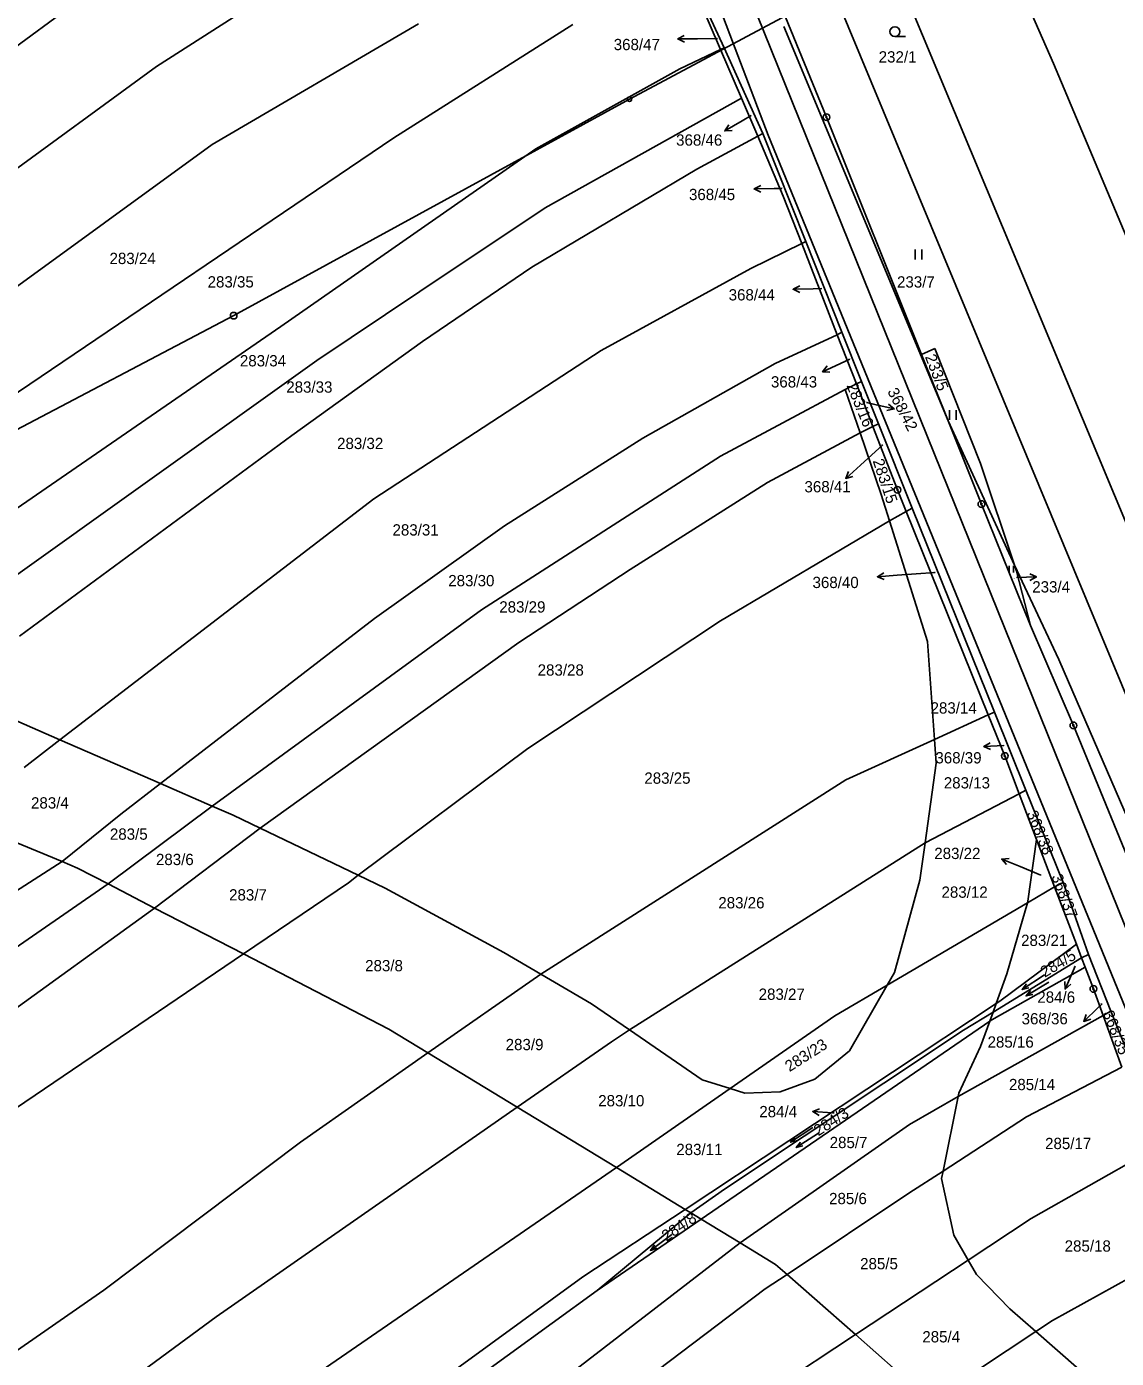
# Model space of a CAD drawing. Extents: x -762263 to -760336, y -1154405 to -1152076.
# Drawn here: x -761541.7 to -761377.6, y -1152988.8 to -1152788.2 of the extents above; entities that cross this region are included whole.
import ezdxf

# ---------------------------------------------------------------- set-up
doc = ezdxf.new("R2010")
doc.units = 0
for name, color, linetype in [('Vrstva 1', 7, 'Continuous'), ('Vrstva 12', 7, 'Continuous'), ('Vrstva 16', 7, 'Continuous'), ('Vrstva 18', 7, 'Continuous'), ('Vrstva 24', 7, 'Continuous'), ('Vrstva 25', 7, 'Continuous'), ('Vrstva 26', 7, 'Continuous'), ('Vrstva 4', 7, 'Continuous'), ('Vrstva 6', 7, 'Continuous')]:
    doc.layers.add(name, color=color, linetype=linetype)

msp = doc.modelspace()

# ---------------------------------------------------------------- linework, layer by layer
at = {"layer": 'Vrstva 1'}
for p, q in [((-761359.06, -1152904.05), (-761421.84, -1152753.46)), ((-761365.51, -1152914.59), (-761431.48, -1152755.68)), ((-761421.27, -1152801.84), (-761434.72, -1152768.97)), ((-761522.15, -1152794.2), (-761488.72, -1152772.8)), ((-761443.12, -1152777.85), (-761437.22, -1152791.63)), ((-761442.95, -1152777.74), (-761436.7, -1152791.39)), ((-761530.76, -1152781.96), (-761631.52, -1152856.45)), ((-761482.68, -1152787.79), (-761513.77, -1152805.94)), ((-761427.68, -1152788.2), (-761402.97, -1152847.56)), ((-761437.22, -1152791.63), (-761436.7, -1152791.39)), ((-761434.07, -1152798.99), (-761437.22, -1152791.63)), ((-761436.7, -1152791.39), (-761430.84, -1152804.3)), ((-761616.57, -1152863.14), (-761522.15, -1152794.2)), ((-761431.62, -1152804.72), (-761434.07, -1152798.99)), ((-761421.27, -1152801.84), (-761406.97, -1152837.57)), ((-761430.84, -1152804.3), (-761431.62, -1152804.72)), ((-761427.77, -1152813.73), (-761431.62, -1152804.72)), ((-761430.84, -1152804.3), (-761424.39, -1152820.54)), ((-761513.77, -1152805.94), (-761600.5, -1152869.06)), ((-761425, -1152820.84), (-761427.77, -1152813.73)), ((-761424.39, -1152820.54), (-761425, -1152820.84)), ((-761425, -1152820.84), (-761419.66, -1152834.6)), ((-761418.98, -1152834.22), (-761424.39, -1152820.54)), ((-761419.66, -1152834.6), (-761418.98, -1152834.22)), ((-761419.66, -1152834.6), (-761416.77, -1152842.02)), ((-761416, -1152841.65), (-761418.98, -1152834.22)), ((-761406.97, -1152837.57), (-761404.98, -1152836.67)), ((-761398.08, -1152853.99), (-761404.98, -1152836.67)), ((-761406.97, -1152837.57), (-761402.97, -1152847.56)), ((-761416.77, -1152842.02), (-761418.44, -1152842.83)), ((-761418.44, -1152842.83), (-761416.19, -1152849.39)), ((-761416.77, -1152842.02), (-761416, -1152841.65)), ((-761416.77, -1152842.02), (-761414.28, -1152848.44)), ((-761413.45, -1152848.03), (-761416, -1152841.65)), ((-761416.19, -1152849.39), (-761414.28, -1152848.44)), ((-761414.28, -1152848.44), (-761413.45, -1152848.03)), ((-761414.28, -1152848.44), (-761410.58, -1152857.95)), ((-761408.38, -1152860.71), (-761413.45, -1152848.03)), ((-761402.97, -1152847.56), (-761397.95, -1152860.1)), ((-761392.98, -1152869.29), (-761402.97, -1152847.56)), ((-761413.02, -1152858.65), (-761416.19, -1152849.39)), ((-761392.98, -1152869.29), (-761398.08, -1152853.99)), ((-761411.76, -1152862.64), (-761413.02, -1152858.65)), ((-761410.58, -1152857.95), (-761409.26, -1152861.24)), ((-761409.26, -1152861.24), (-761408.38, -1152860.71)), ((-761396, -1152891.44), (-761408.38, -1152860.71)), ((-761390.56, -1152878.39), (-761397.95, -1152860.1)), ((-761411.76, -1152862.64), (-761409.26, -1152861.24)), ((-761406.04, -1152880.82), (-761411.76, -1152862.64)), ((-761409.26, -1152861.24), (-761396.92, -1152891.86)), ((-761392.67, -1152870.22), (-761392.98, -1152869.29)), ((-761390.56, -1152878.39), (-761392.67, -1152870.22)), ((-761384.1, -1152893.43), (-761390.56, -1152878.39)), ((-761405.02, -1152895.55), (-761406.04, -1152880.82)), ((-761553.98, -1152888.06), (-761536.69, -1152895.6)), ((-761405.02, -1152895.55), (-761396.92, -1152891.86)), ((-761396.92, -1152891.86), (-761396, -1152891.44)), ((-761396.92, -1152891.86), (-761394.43, -1152898.04)), ((-761391.26, -1152903.19), (-761396, -1152891.44)), ((-761384.1, -1152893.43), (-761369.9, -1152928.1)), ((-761536.69, -1152895.6), (-761542.07, -1152899.78)), ((-761521.55, -1152902.2), (-761536.69, -1152895.6)), ((-761404.77, -1152899.14), (-761405.02, -1152895.55)), ((-761394.43, -1152898.04), (-761392.27, -1152903.72)), ((-761406.43, -1152911.14), (-761404.77, -1152899.14)), ((-761527.52, -1152906.82), (-761521.55, -1152902.2)), ((-761521.55, -1152902.2), (-761513.75, -1152905.6)), ((-761406.43, -1152911.14), (-761392.27, -1152903.72)), ((-761392.27, -1152903.72), (-761391.26, -1152903.19)), ((-761392.27, -1152903.72), (-761389.65, -1152910.6)), ((-761385.66, -1152917.1), (-761391.26, -1152903.19)), ((-761536.35, -1152913.95), (-761527.52, -1152906.82)), ((-761513.75, -1152905.6), (-761529.44, -1152917.29)), ((-761510.61, -1152906.97), (-761513.75, -1152905.6)), ((-761506.54, -1152908.92), (-761510.61, -1152906.97)), ((-761552.17, -1152907.36), (-761536.35, -1152913.95)), ((-761522.42, -1152920.93), (-761506.54, -1152908.92)), ((-761506.54, -1152908.92), (-761491.78, -1152915.98)), ((-761407.21, -1152916.73), (-761406.43, -1152911.14)), ((-761389.65, -1152910.6), (-761390.94, -1152919.91)), ((-761389.65, -1152910.6), (-761386.93, -1152917.76)), ((-761534.03, -1152914.92), (-761536.35, -1152913.95)), ((-761529.44, -1152917.29), (-761534.03, -1152914.92)), ((-761493.25, -1152917.15), (-761509.05, -1152927.85)), ((-761491.78, -1152915.98), (-761493.25, -1152917.15)), ((-761491.78, -1152915.98), (-761487.69, -1152917.94)), ((-761411.03, -1152930.63), (-761407.21, -1152916.73)), ((-761386.93, -1152917.76), (-761385.66, -1152917.1)), ((-761381.82, -1152927.94), (-761385.66, -1152917.1)), ((-761529.44, -1152917.29), (-761522.42, -1152920.93)), ((-761487.69, -1152917.94), (-761469.83, -1152927.65)), ((-761386.93, -1152917.76), (-761391.01, -1152920.15)), ((-761383.65, -1152926.38), (-761386.93, -1152917.76)), ((-761509.05, -1152927.85), (-761522.42, -1152920.93)), ((-761391.01, -1152920.15), (-761412.14, -1152932.56)), ((-761394.12, -1152930.85), (-761391.01, -1152920.15)), ((-761390.94, -1152919.91), (-761391.01, -1152920.15)), ((-761383.65, -1152926.38), (-761395.19, -1152934.94)), ((-761382.87, -1152928.44), (-761383.65, -1152926.38)), ((-761487.15, -1152939.18), (-761509.05, -1152927.85)), ((-761469.83, -1152927.65), (-761464.29, -1152930.88)), ((-761396.2, -1152936.6), (-761382.87, -1152928.44)), ((-761382.87, -1152928.44), (-761381.82, -1152927.94)), ((-761382.34, -1152929.84), (-761382.87, -1152928.44)), ((-761378.44, -1152936.46), (-761381.82, -1152927.94)), ((-761464.29, -1152930.88), (-761481.27, -1152942.76)), ((-761464.29, -1152930.88), (-761456.63, -1152935.35)), ((-761412.14, -1152932.56), (-761411.03, -1152930.63)), ((-761396.36, -1152937.75), (-761382.34, -1152929.84)), ((-761395.73, -1152935.3), (-761394.12, -1152930.85)), ((-761382.34, -1152929.84), (-761381.09, -1152933.12)), ((-761420, -1152937.18), (-761412.14, -1152932.56)), ((-761412.14, -1152932.56), (-761417.82, -1152942.45)), ((-761381.09, -1152933.12), (-761379.64, -1152937.13)), ((-761395.19, -1152934.94), (-761395.73, -1152935.3)), ((-761456.63, -1152935.35), (-761450.92, -1152939.28)), ((-761442.56, -1152966.31), (-761395.73, -1152935.3)), ((-761435.76, -1152948.12), (-761420, -1152937.18)), ((-761400.66, -1152939.33), (-761396.2, -1152936.6)), ((-761396.2, -1152936.6), (-761396.7, -1152937.98)), ((-761395.73, -1152935.3), (-761396.2, -1152936.6)), ((-761379.64, -1152937.13), (-761378.44, -1152936.46)), ((-761379.64, -1152937.13), (-761376.82, -1152944.89)), ((-761375.4, -1152944.06), (-761378.44, -1152936.46)), ((-761481.27, -1152942.76), (-761487.15, -1152939.18)), ((-761440.13, -1152967.78), (-761396.7, -1152937.98)), ((-761396.7, -1152937.98), (-761398.08, -1152941.79)), ((-761396.7, -1152937.98), (-761396.36, -1152937.75)), ((-761453.65, -1152941.06), (-761467.83, -1152950.93)), ((-761450.92, -1152939.28), (-761453.65, -1152941.06)), ((-761439.98, -1152946.79), (-761450.92, -1152939.28)), ((-761436.62, -1152963.26), (-761400.66, -1152939.33)), ((-761467.83, -1152950.93), (-761481.27, -1152942.76)), ((-761417.82, -1152942.45), (-761423.02, -1152946.7)), ((-761398.08, -1152941.79), (-761401.34, -1152948.8)), ((-761435.76, -1152948.12), (-761439.98, -1152946.79)), ((-761423.02, -1152946.7), (-761428.23, -1152948.59)), ((-761452.9, -1152960.02), (-761435.76, -1152948.12)), ((-761433.56, -1152948.82), (-761435.76, -1152948.12)), ((-761428.23, -1152948.59), (-761433.56, -1152948.82)), ((-761401.34, -1152948.8), (-761401.44, -1152949.31)), ((-761467.83, -1152950.93), (-761452.9, -1152960.02)), ((-761408.78, -1152953.55), (-761401.44, -1152949.31)), ((-761401.44, -1152949.31), (-761403.72, -1152960.54)), ((-761434.28, -1152971.34), (-761408.78, -1152953.55)), ((-761442.56, -1152966.31), (-761452.9, -1152960.02)), ((-761408.87, -1152963.89), (-761403.72, -1152960.54)), ((-761403.72, -1152960.54), (-761403.95, -1152961.67)), ((-761441.67, -1152966.85), (-761436.62, -1152963.26)), ((-761403.95, -1152961.67), (-761402.11, -1152970.21)), ((-761427.21, -1152976.11), (-761408.87, -1152963.89)), ((-761457.93, -1152976.48), (-761442.56, -1152966.31)), ((-761442.56, -1152966.31), (-761441.67, -1152966.85)), ((-761441.67, -1152966.85), (-761440.13, -1152967.78)), ((-761455.81, -1152978.54), (-761440.13, -1152967.78)), ((-761440.13, -1152967.78), (-761434.28, -1152971.34)), ((-761402.11, -1152970.21), (-761399.94, -1152973.96)), ((-761428.93, -1152974.6), (-761434.28, -1152971.34)), ((-761427.21, -1152976.11), (-761428.93, -1152974.6)), ((-761416.92, -1152985.16), (-761399.94, -1152973.96)), ((-761399.94, -1152973.96), (-761398.68, -1152976.14)), ((-761550.95, -1153044.04), (-761457.93, -1152976.48)), ((-761416.92, -1152985.16), (-761427.21, -1152976.11)), ((-761398.68, -1152976.14), (-761393.65, -1152981.27)), ((-761455.81, -1152978.54), (-761548.99, -1153046.04)), ((-761393.65, -1152981.27), (-761389.73, -1152984.7)), ((-761405.57, -1152995.15), (-761416.92, -1152985.16)), ((-761405.57, -1152995.15), (-761389.73, -1152984.7)), ((-761389.73, -1152984.7), (-761379.16, -1152993.96))]:
    msp.add_line(p, q, dxfattribs=at)
at = {"layer": 'Vrstva 12'}
for p, q in [((-761450.93, -1152799.12), (-761389.45, -1152766.26)), ((-761450.93, -1152799.12), (-761510.52, -1152831.73)), ((-761510.52, -1152831.73), (-761578.61, -1152867.5))]:
    msp.add_line(p, q, dxfattribs=at)
at = {"layer": 'Vrstva 16'}
for p, q in [((-761443.67, -1152790.054), (-761440.67, -1152790.02)), ((-761437.67, -1152789.98), (-761440.67, -1152790.02)), ((-761436.592, -1152803.904), (-761433.99, -1152802.41)), ((-761432.6, -1152801.61), (-761433.99, -1152802.41)), ((-761432.17, -1152812.632), (-761429.17, -1152812.58)), ((-761428, -1152812.56), (-761429.17, -1152812.58)), ((-761426.289, -1152827.744), (-761423.29, -1152827.68)), ((-761421.96, -1152827.65), (-761423.29, -1152827.68)), ((-761421.86, -1152840.185), (-761419.14, -1152838.92)), ((-761417.77, -1152838.28), (-761419.14, -1152838.92)), ((-761415.27, -1152844.8), (-761414, -1152845.09)), ((-761411.077, -1152845.766), (-761414, -1152845.09)), ((-761412.77, -1152851.2), (-761416.15, -1152854.23)), ((-761418.383, -1152856.233), (-761416.15, -1152854.23)), ((-761413.612, -1152871.052), (-761410.62, -1152870.83)), ((-761404.91, -1152870.4), (-761410.62, -1152870.83)), ((-761389.671, -1152871.075), (-761392.67, -1152871.14)), ((-761397.587, -1152896.61), (-761394.59, -1152896.48)), ((-761394.57, -1152896.48), (-761394.59, -1152896.48)), ((-761394.894, -1152913.557), (-761392.12, -1152914.7)), ((-761388.99, -1152915.99), (-761392.12, -1152914.7)), ((-761385.351, -1152933.135), (-761384.14, -1152930.39)), ((-761383.84, -1152929.71), (-761384.14, -1152930.39)), ((-761382.55, -1152938.012), (-761380.39, -1152935.93)), ((-761379.78, -1152935.34), (-761380.39, -1152935.93)), ((-761423.344, -1152951.595), (-761420.35, -1152951.78)), ((-761420.12, -1152951.79), (-761420.35, -1152951.78))]:
    msp.add_line(p, q, dxfattribs=at)
for points in [[(-761442.664, -1152790.542), (-761443.67, -1152790.054), (-761442.675, -1152789.542)], [(-761435.475, -1152803.839), (-761436.592, -1152803.904), (-761435.973, -1152802.972)], [(-761431.161, -1152813.114), (-761432.17, -1152812.632), (-761431.178, -1152812.114)], [(-761425.279, -1152828.222), (-761426.289, -1152827.744), (-761425.3, -1152827.223)], [(-761420.743, -1152840.217), (-761421.86, -1152840.185), (-761421.164, -1152839.31)], [(-761411.939, -1152845.054), (-761411.077, -1152845.766), (-761412.164, -1152846.028)], [(-761417.305, -1152855.938), (-761418.383, -1152856.233), (-761417.973, -1152855.193)], [(-761412.577, -1152871.477), (-761413.612, -1152871.052), (-761412.652, -1152870.48)], [(-761390.681, -1152870.597), (-761389.671, -1152871.075), (-761390.66, -1152871.597)], [(-761396.567, -1152897.066), (-761397.587, -1152896.61), (-761396.61, -1152896.067)], [(-761394.16, -1152914.4), (-761394.894, -1152913.557), (-761393.779, -1152913.476)], [(-761384.49, -1152932.422), (-761385.351, -1152933.135), (-761385.405, -1152932.018)], [(-761381.483, -1152937.678), (-761382.55, -1152938.012), (-761382.177, -1152936.958)], [(-761422.377, -1152952.156), (-761423.344, -1152951.595), (-761422.315, -1152951.157)]]:
    msp.add_lwpolyline(points, dxfattribs=at)
at = {"layer": 'Vrstva 24'}
for centre, radius in [((-761421.27, -1152801.84), 0.5), ((-761421.27, -1152801.84), 0.1), ((-761410.58, -1152857.95), 0.5), ((-761410.58, -1152857.95), 0.1), ((-761397.95, -1152860.1), 0.5), ((-761397.95, -1152860.1), 0.1), ((-761384.1, -1152893.43), 0.5), ((-761384.1, -1152893.43), 0.1), ((-761394.43, -1152898.04), 0.5), ((-761394.43, -1152898.04), 0.1), ((-761381.09, -1152933.12), 0.5), ((-761381.09, -1152933.12), 0.1)]:
    msp.add_circle(centre, radius, dxfattribs=at)
at = {"layer": 'Vrstva 25'}
for p, q in [((-761410.97, -1152789.71), (-761409.37, -1152789.71)), ((-761407.94, -1152823.25), (-761407.94, -1152821.75)), ((-761406.94, -1152823.25), (-761406.94, -1152821.75)), ((-761402.73, -1152847.44), (-761402.73, -1152845.94)), ((-761401.73, -1152847.44), (-761401.73, -1152845.94)), ((-761393.765, -1152870.41), (-761393.765, -1152869.405)), ((-761393.095, -1152870.41), (-761393.095, -1152869.405))]:
    msp.add_line(p, q, dxfattribs=at)
for points in [[(-761388.448, -1152930.999), (-761391.812, -1152933.201), (-761390.788, -1152932.931)], [(-761391.812, -1152933.201), (-761391.154, -1152932.37)], [(-761387.788, -1152932.092), (-761391.232, -1152934.168), (-761390.198, -1152933.936)], [(-761391.232, -1152934.168), (-761390.544, -1152933.362)], [(-761423.312, -1152953.993), (-761426.668, -1152956.207), (-761425.644, -1152955.933)], [(-761422.465, -1152954.825), (-761425.835, -1152957.015), (-761424.81, -1152956.749)], [(-761426.668, -1152956.207), (-761426.013, -1152955.374)], [(-761425.835, -1152957.015), (-761425.175, -1152956.187)], [(-761444.557, -1152970.101), (-761447.783, -1152972.499), (-761446.777, -1152972.169)], [(-761447.783, -1152972.499), (-761447.176, -1152971.631)]]:
    msp.add_lwpolyline(points, dxfattribs=at)
msp.add_circle((-761410.97, -1152788.96), 0.75, dxfattribs=at)
at = {"layer": 'Vrstva 26'}
for centre, radius in [((-761450.93, -1152799.12), 0.335), ((-761510.52, -1152831.73), 0.5)]:
    msp.add_circle(centre, radius, dxfattribs=at)
at = {"layer": 'Vrstva 4'}
for p, q in [((-761435.81, -1152776.3), (-761364.68, -1152952.56)), ((-761440.38, -1152777.38), (-761430.06, -1152804.55)), ((-761371.29, -1152948.19), (-761430.06, -1152804.55))]:
    msp.add_line(p, q, dxfattribs=at)
at = {"layer": 'Vrstva 6'}
for p, q in [((-761396.79, -1152771.69), (-761387.09, -1152793.76)), ((-761486.39, -1152804.93), (-761459.45, -1152787.9)), ((-761443.33, -1152794.57), (-761437.22, -1152791.63)), ((-761465.01, -1152806.63), (-761443.33, -1152794.57)), ((-761387.09, -1152793.76), (-761351.43, -1152878.67)), ((-761463.64, -1152815.49), (-761434.07, -1152798.99)), ((-761440.78, -1152809.68), (-761431.62, -1152804.72)), ((-761547.2, -1152846.06), (-761486.39, -1152804.93)), ((-761503.4, -1152833.34), (-761465.01, -1152806.63)), ((-761465.64, -1152824.41), (-761440.78, -1152809.68)), ((-761482.48, -1152828.11), (-761463.64, -1152815.49)), ((-761432.67, -1152824.65), (-761425, -1152820.84)), ((-761482.1, -1152835.64), (-761465.64, -1152824.41)), ((-761455.19, -1152837), (-761432.67, -1152824.65)), ((-761498.02, -1152838.47), (-761482.48, -1152828.11)), ((-761503.4, -1152833.34), (-761547.91, -1152863.99)), ((-761419.66, -1152834.6), (-761429, -1152838.91)), ((-761501.78, -1152849.8), (-761482.1, -1152835.64)), ((-761498.02, -1152838.47), (-761547.43, -1152873.8)), ((-761489.41, -1152859.32), (-761455.19, -1152837)), ((-761429, -1152838.91), (-761448.92, -1152850.19)), ((-761437.21, -1152852.9), (-761418.44, -1152842.83)), ((-761542.75, -1152880.01), (-761501.78, -1152849.8)), ((-761469.74, -1152863.39), (-761448.92, -1152850.19)), ((-761430.14, -1152856.87), (-761416.19, -1152849.39)), ((-761473.22, -1152876.04), (-761437.21, -1152852.9)), ((-761430.14, -1152856.87), (-761450.85, -1152869.97)), ((-761536.69, -1152895.6), (-761489.41, -1152859.32)), ((-761437.23, -1152877.69), (-761411.76, -1152862.64)), ((-761489.34, -1152877.31), (-761469.74, -1152863.39)), ((-761450.85, -1152869.97), (-761467.61, -1152880.94)), ((-761386.27, -1152883.5), (-761392.98, -1152869.29)), ((-761513.75, -1152905.6), (-761473.22, -1152876.04)), ((-761489.34, -1152877.31), (-761521.55, -1152902.2)), ((-761466.23, -1152896.93), (-761437.23, -1152877.69)), ((-761506.54, -1152908.92), (-761467.61, -1152880.94)), ((-761362.82, -1152937.87), (-761386.27, -1152883.5)), ((-761491.78, -1152915.98), (-761466.23, -1152896.93)), ((-761405.02, -1152895.55), (-761418.34, -1152901.61)), ((-761418.34, -1152901.61), (-761464.29, -1152930.88)), ((-761406.43, -1152911.14), (-761450.92, -1152939.28)), ((-761567.14, -1152933.62), (-761536.35, -1152913.95)), ((-761562.87, -1152940.38), (-761529.44, -1152917.29)), ((-761551.11, -1152941.64), (-761522.42, -1152920.93)), ((-761550.29, -1152955.78), (-761509.05, -1152927.85)), ((-761401.44, -1152949.31), (-761379.64, -1152937.13)), ((-761500.48, -1152956.19), (-761481.27, -1152942.76)), ((-761391.16, -1152952.37), (-761376.82, -1152944.89)), ((-761513.15, -1152982.49), (-761467.83, -1152950.93)), ((-761403.72, -1152960.54), (-761391.16, -1152952.37)), ((-761530.07, -1152978.48), (-761500.48, -1152956.19)), ((-761390.45, -1152967.71), (-761372.29, -1152957.39)), ((-761507.97, -1152997.92), (-761452.9, -1152960.02)), ((-761441.67, -1152966.85), (-761455.81, -1152978.54)), ((-761399.94, -1152973.96), (-761390.45, -1152967.71)), ((-761434.28, -1152971.34), (-761464.1, -1152994.32)), ((-761387.24, -1152983.06), (-761367.06, -1152971.83)), ((-761430.49, -1152978.3), (-761427.21, -1152976.11)), ((-761530.07, -1152978.48), (-761560.47, -1152999.59)), ((-761514.47, -1153041.72), (-761430.49, -1152978.3)), ((-761592.56, -1153040.79), (-761513.15, -1152982.49)), ((-761389.73, -1152984.7), (-761387.24, -1152983.06)), ((-761431.46, -1152994.74), (-761416.92, -1152985.16))]:
    msp.add_line(p, q, dxfattribs=at)

# ---------------------------------------------------------------- texts
at = {"layer": 'Vrstva 16'}
for s, p in [('368/47', (-761453.3, -1152791.75)), ('368/46', (-761443.91, -1152806.13)), ('368/45', (-761441.974, -1152814.33)), ('368/44', (-761436, -1152829.44)), ('368/43', (-761429.635, -1152842.55)), ('368/41', (-761424.584, -1152858.34)), ('368/40', (-761423.374, -1152872.75)), ('233/4', (-761390.293, -1152873.42)), ('368/39', (-761404.875, -1152899.16)), ('283/22', (-761405.042, -1152913.56)), ('284/6', (-761389.525, -1152935.2)), ('368/36', (-761391.895, -1152938.45)), ('284/4', (-761431.385, -1152952.44))]:
    msp.add_text(s, height=1.7, dxfattribs=at).set_placement(p)
msp.add_text('368/42', height=1.7, rotation=297.36509, dxfattribs=at).set_placement((-761412.151, -1152843.132))
at = {"layer": 'Vrstva 18'}
for s, height, p in [('368/47', 0.1, (-761437.917, -1152789.98)), ('232/1', 1.7, (-761413.413, -1152793.61)), ('368/46', 0.1, (-761432.849, -1152801.61)), ('368/45', 0.1, (-761428.252, -1152812.56)), ('283/24', 1.7, (-761529.214, -1152823.96)), ('283/35', 1.7, (-761514.444, -1152827.49)), ('233/7', 1.7, (-761410.651, -1152827.5)), ('368/44', 0.1, (-761422.209, -1152827.65)), ('283/34', 1.7, (-761509.587, -1152839.37)), ('368/43', 0.1, (-761418.024, -1152838.28)), ('283/33', 1.7, (-761502.604, -1152843.33)), ('368/42', 0.1, (-761415.524, -1152844.8)), ('283/32', 1.7, (-761494.951, -1152851.82)), ('368/41', 0.1, (-761412.999, -1152851.2)), ('283/31', 1.7, (-761486.609, -1152864.84)), ('283/30', 1.7, (-761478.214, -1152872.48)), ('368/40', 0.1, (-761405.161, -1152870.4)), ('233/4', 0.1, (-761393.127, -1152871.38)), ('283/29', 1.7, (-761470.534, -1152876.44)), ('283/28', 1.7, (-761464.754, -1152885.94)), ('283/14', 1.7, (-761405.602, -1152891.65)), ('368/39', 0.1, (-761394.824, -1152896.48)), ('283/25', 1.7, (-761448.69, -1152902.22)), ('283/13', 1.7, (-761403.609, -1152902.93)), ('283/4', 1.7, (-761541.031, -1152905.95)), ('283/5', 1.7, (-761529.157, -1152910.65)), ('283/6', 1.7, (-761522.221, -1152914.47)), ('283/22', 0.1, (-761389.252, -1152915.99)), ('283/7', 1.7, (-761511.21, -1152919.8)), ('283/12', 1.7, (-761403.956, -1152919.39)), ('283/26', 1.7, (-761437.554, -1152920.99)), ('283/21', 1.7, (-761391.973, -1152926.65)), ('283/8', 1.7, (-761490.731, -1152930.46)), ('284/6', 0.1, (-761384.048, -1152929.71)), ('283/27', 1.7, (-761431.483, -1152934.76)), ('368/36', 0.1, (-761380.034, -1152935.34)), ('283/9', 1.7, (-761469.571, -1152942.34)), ('285/16', 1.7, (-761397.022, -1152941.96)), ('285/14', 1.7, (-761393.802, -1152948.36)), ('283/10', 1.7, (-761455.639, -1152950.8)), ('284/4', 0.1, (-761420.328, -1152951.79)), ('283/11', 1.7, (-761443.883, -1152958.14)), ('285/7', 1.7, (-761420.793, -1152957.09)), ('285/17', 1.7, (-761388.362, -1152957.24)), ('285/6', 1.7, (-761420.88, -1152965.53)), ('285/18', 1.7, (-761385.412, -1152972.68)), ('285/5', 1.7, (-761416.207, -1152975.34)), ('285/4', 1.7, (-761406.84, -1152986.35))]:
    msp.add_text(s, height=height, dxfattribs=at).set_placement(p)
for s, rotation, p in [('233/5', 291.00526, (-761406.466, -1152837.92)), ('283/16', 292.26577, (-761418.291, -1152842.244)), ('283/15', 288.54154, (-761414.335, -1152853.589)), ('368/38', 292.03659, (-761391.17, -1152906.664)), ('368/37', 290.71879, (-761387.445, -1152916.174)), ('284/5', 30.88243, (-761388.413, -1152931.448)), ('368/35', 291.75011, (-761379.709, -1152936.751)), ('283/23', 32.48671, (-761426.841, -1152945.661)), ('284/3', 33.00237, (-761422.496, -1152955.332)), ('284/8', 33.9191, (-761445.369, -1152971.213))]:
    msp.add_text(s, height=1.7, rotation=rotation, dxfattribs=at).set_placement(p)

doc.saveas('drawing.dxf')
